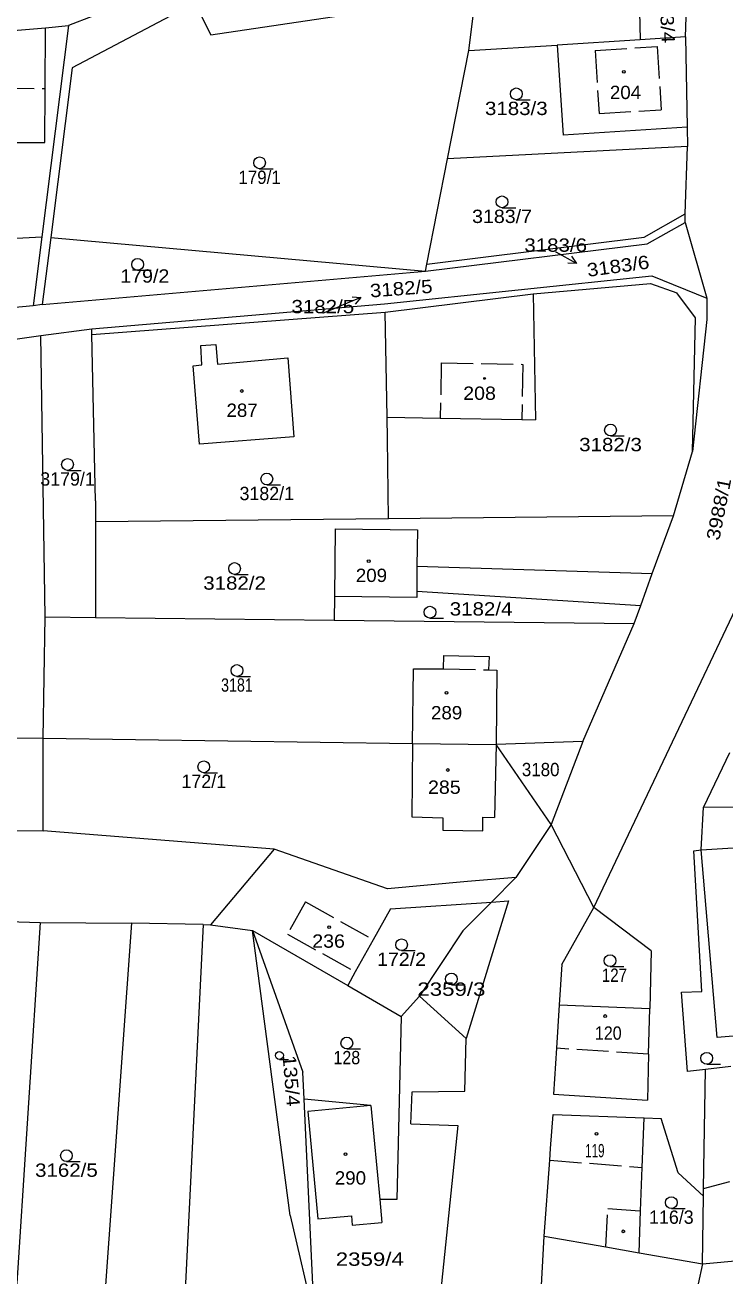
# Model space of a CAD drawing. Extents: x -590528 to -586543, y -1119609 to -1116685.
# Drawn here: x -588698 to -588608.7, y -1118281.3 to -1118121.8 of the extents above; entities that cross this region are included whole.
import ezdxf
from ezdxf.enums import TextEntityAlignment as Align

# ---------------------------------------------------------------- set-up
doc = ezdxf.new("R2010")
doc.units = 0
doc.header["$LTSCALE"] = 0.68
doc.linetypes.add('LONG_DASHED', pattern=[7.5, 6, -1.5])
for name, color, linetype, lineweight in [('1', 7, 'Continuous', 13), ('2', 7, 'LONG_DASHED', 13), ('3', 7, 'Continuous', 13), ('6', 7, 'Continuous', 13)]:
    doc.layers.add(name, color=color, linetype=linetype, lineweight=lineweight)

msp = doc.modelspace()

# ---------------------------------------------------------------- linework, layer by layer
at = {"layer": '1'}
for p, q in [((-588677.57, -1118116.13), (-588692.41, -1118121.83)), ((-588619.63, -1118115.95), (-588619.5, -1118123.67)), ((-588641.32, -1118125.05), (-588640.3, -1118116.83)), ((-588713.9, -1118123.63), (-588695.33, -1118122.16)), ((-588692.41, -1118121.83), (-588695.82, -1118148.8)), ((-588695.33, -1118122.16), (-588692.41, -1118121.83)), ((-588641.32, -1118125.05), (-588630.05, -1118124.34)), ((-588630.05, -1118124.34), (-588629.3, -1118135.83)), ((-588691.92, -1118127.24), (-588694.67, -1118148.9)), ((-588613.48, -1118134.81), (-588629.3, -1118135.83)), ((-588711.12, -1118136.71), (-588695.41, -1118136.78)), ((-588613.44, -1118137.3), (-588644.04, -1118138.87)), ((-588613.76, -1118146.98), (-588610.98, -1118156.63)), ((-588714.7, -1118149.82), (-588695.82, -1118148.8)), ((-588695.82, -1118148.8), (-588696.93, -1118157.62)), ((-588694.67, -1118148.9), (-588695.75, -1118157.42)), ((-588694.67, -1118148.9), (-588646.86, -1118153.18)), ((-588652.03, -1118158.43), (-588633.12, -1118156.09)), ((-588633.12, -1118156.09), (-588632.85, -1118172.15)), ((-588612.41, -1118159.15), (-588614.81, -1118155.95)), ((-588696.93, -1118157.62), (-588714.99, -1118159.28)), ((-588695.75, -1118157.42), (-588696.93, -1118157.62)), ((-588689.45, -1118160.52), (-588652.08, -1118157.36)), ((-588689.43, -1118161.26), (-588652.03, -1118158.43)), ((-588695.4, -1118197.29), (-588695.94, -1118161.41)), ((-588651.76, -1118171.81), (-588644.98, -1118171.93)), ((-588651.6, -1118184.77), (-588651.7, -1118174.57)), ((-588688.98, -1118182.48), (-588688.98, -1118185.17)), ((-588651.6, -1118184.77), (-588688.98, -1118185.17)), ((-588688.98, -1118185.17), (-588688.98, -1118197.36)), ((-588615.21, -1118184.38), (-588651.6, -1118184.77)), ((-588617.93, -1118191.74), (-588615.21, -1118184.38)), ((-588658.39, -1118186.06), (-588658.48, -1118194.7)), ((-588647.95, -1118190.83), (-588617.93, -1118191.74)), ((-588658.48, -1118194.7), (-588658.51, -1118197.7)), ((-588647.99, -1118194.02), (-588619.41, -1118195.81)), ((-588625.37, -1118234.33), (-588606.07, -1118193.71)), ((-588688.98, -1118197.36), (-588658.51, -1118197.7)), ((-588658.51, -1118197.7), (-588620.26, -1118198.13)), ((-588626.81, -1118213.18), (-588620.26, -1118198.13)), ((-588695.65, -1118212.77), (-588648.51, -1118213.43)), ((-588695.62, -1118224.58), (-588695.65, -1118212.77)), ((-588648.51, -1118213.43), (-588637.87, -1118213.55)), ((-588637.87, -1118213.55), (-588638.07, -1118222.85)), ((-588626.81, -1118213.18), (-588637.87, -1118213.55)), ((-588630.84, -1118223.78), (-588637.87, -1118213.55)), ((-588608.08, -1118214.62), (-588611.39, -1118221.57)), ((-588611.7, -1118227.01), (-588611.39, -1118221.57)), ((-588592.82, -1118221.58), (-588611.39, -1118221.57)), ((-588639.53, -1118224.55), (-588639.53, -1118222.84)), ((-588639.53, -1118222.84), (-588638.07, -1118222.85)), ((-588753.83, -1118223.97), (-588695.62, -1118224.58)), ((-588625.37, -1118234.33), (-588630.84, -1118223.78)), ((-588612.65, -1118227.1), (-588611.7, -1118227.01)), ((-588611.63, -1118245.06), (-588612.65, -1118227.1)), ((-588609.65, -1118250.91), (-588611.7, -1118227.01)), ((-588635.35, -1118230.51), (-588641.52, -1118231.05)), ((-588651.34, -1118234.53), (-588653.53, -1118238.46)), ((-588651.34, -1118234.53), (-588638.46, -1118233.65)), ((-588636.27, -1118233.5), (-588641.69, -1118251.06)), ((-588638.46, -1118233.65), (-588636.27, -1118233.5)), ((-588629.49, -1118241.6), (-588625.37, -1118234.33)), ((-588618.07, -1118239.88), (-588625.37, -1118234.33)), ((-588705.15, -1118235.97), (-588696.04, -1118236.25)), ((-588696.04, -1118236.25), (-588704.69, -1118371.28)), ((-588696.04, -1118236.25), (-588684.37, -1118236.36)), ((-588684.37, -1118236.36), (-588690.78, -1118326.07)), ((-588675.24, -1118236.53), (-588684.37, -1118236.36)), ((-588675.24, -1118236.53), (-588679.96, -1118332.69)), ((-588675.24, -1118236.53), (-588674.3, -1118236.55)), ((-588668.95, -1118237.26), (-588662.51, -1118255.33)), ((-588664.12, -1118273.62), (-588668.95, -1118237.26)), ((-588642.09, -1118237.31), (-588647.65, -1118245.64)), ((-588653.53, -1118238.46), (-588655.82, -1118242.57)), ((-588618.07, -1118239.88), (-588618.26, -1118247.21)), ((-588655.82, -1118242.57), (-588656.79, -1118244.3)), ((-588629.49, -1118241.6), (-588629.82, -1118246.78)), ((-588614.21, -1118245.16), (-588611.63, -1118245.06)), ((-588613.43, -1118255.27), (-588614.21, -1118245.16)), ((-588629.82, -1118246.78), (-588630.17, -1118252.31)), ((-588629.82, -1118246.78), (-588618.26, -1118247.21)), ((-588618.41, -1118253.05), (-588618.26, -1118247.21)), ((-588649.96, -1118248.26), (-588650.54, -1118271.58)), ((-588630.17, -1118252.31), (-588630.54, -1118258.15)), ((-588618.41, -1118253.05), (-588618.56, -1118258.91)), ((-588662.35, -1118258.78), (-588662.51, -1118255.33)), ((-588611.39, -1118270.2), (-588611.15, -1118255)), ((-588630.54, -1118258.15), (-588618.56, -1118258.91)), ((-588653.83, -1118259.6), (-588662.35, -1118258.78)), ((-588630.9, -1118265.08), (-588630.59, -1118260.75)), ((-588614.65, -1118268.2), (-588616.79, -1118261.25)), ((-588611.4, -1118271.16), (-588614.65, -1118268.2)), ((-588611.39, -1118270.2), (-588608.03, -1118269.31)), ((-588650.54, -1118271.58), (-588652.71, -1118271.58)), ((-588656.21, -1118274.87), (-588652.43, -1118274.53)), ((-588632.53, -1118291.22), (-588631.71, -1118276.27)), ((-588619.62, -1118278.38), (-588611.53, -1118279.79)), ((-588611.53, -1118279.79), (-588612.95, -1118286.29))]:
    msp.add_line(p, q, dxfattribs=at)
for points in [[(-588613.68, -1118123.3), (-588613.44, -1118115.68), (-588612.82, -1118096.34)], [(-588677.57, -1118116.13), (-588676.29, -1118118.98), (-588691.92, -1118127.24)], [(-588676.29, -1118118.98), (-588674.26, -1118123.02), (-588656.48, -1118120.41)], [(-588695.41, -1118136.78), (-588695.37, -1118129.88), (-588695.33, -1118122.16)], [(-588613.68, -1118123.3), (-588619.5, -1118123.67), (-588630.05, -1118124.34)], [(-588613.68, -1118123.3), (-588613.48, -1118134.81), (-588613.44, -1118137.3)], [(-588646.71, -1118152.3), (-588644.04, -1118138.87), (-588641.32, -1118125.05)], [(-588613.76, -1118146.98), (-588613.73, -1118145.86), (-588613.44, -1118137.3)], [(-588646.86, -1118153.18), (-588618.59, -1118149.71), (-588613.76, -1118146.98)], [(-588646.71, -1118152.3), (-588618.95, -1118148.86), (-588613.73, -1118145.86)], [(-588695.75, -1118157.42), (-588646.86, -1118153.18), (-588646.71, -1118152.3)], [(-588652.08, -1118157.36), (-588617.99, -1118153.76), (-588610.98, -1118156.63), (-588610.98, -1118159.33), (-588612.79, -1118176.18)], [(-588633.12, -1118156.09), (-588618.18, -1118154.74), (-588614.81, -1118155.95)], [(-588651.7, -1118174.57), (-588651.76, -1118171.81), (-588652.03, -1118158.43)], [(-588615.21, -1118184.38), (-588612.79, -1118176.18), (-588612.41, -1118159.15)], [(-588701.64, -1118162.19), (-588695.94, -1118161.41), (-588689.45, -1118160.52)], [(-588688.98, -1118182.48), (-588689.43, -1118161.26), (-588689.45, -1118160.52)], [(-588644.98, -1118171.93), (-588634.58, -1118172.12), (-588632.85, -1118172.15)], [(-588658.39, -1118186.06), (-588647.9, -1118186.18), (-588647.95, -1118190.83)], [(-588620.26, -1118198.13), (-588619.41, -1118195.81), (-588617.93, -1118191.74)], [(-588647.99, -1118194.02), (-588647.99, -1118194.82), (-588658.48, -1118194.7)], [(-588695.65, -1118212.77), (-588695.4, -1118197.29), (-588688.98, -1118197.36)], [(-588648.51, -1118213.43), (-588648.39, -1118203.92), (-588644.56, -1118203.89), (-588644.52, -1118202.19)], [(-588644.52, -1118202.19), (-588638.76, -1118202.35), (-588638.81, -1118204.05)], [(-588638.81, -1118204.05), (-588637.78, -1118204.06), (-588637.87, -1118213.55)], [(-588695.65, -1118212.77), (-588722.23, -1118212.91), (-588733.76, -1118212.97), (-588753.56, -1118213.07)], [(-588648.51, -1118213.43), (-588648.59, -1118222.77), (-588644.65, -1118222.93), (-588644.66, -1118224.47), (-588639.53, -1118224.55)], [(-588626.81, -1118213.18), (-588630.84, -1118223.78), (-588635.35, -1118230.51)], [(-588641.52, -1118231.05), (-588651.73, -1118231.95), (-588666.17, -1118226.91), (-588695.62, -1118224.58)], [(-588666.17, -1118226.91), (-588674.3, -1118236.55), (-588668.95, -1118237.26)], [(-588635.35, -1118230.51), (-588638.46, -1118233.65), (-588642.09, -1118237.31)], [(-588668.95, -1118237.26), (-588656.79, -1118244.3), (-588649.96, -1118248.26)], [(-588649.96, -1118248.26), (-588647.65, -1118245.64), (-588641.69, -1118251.06)], [(-588590.42, -1118249.31), (-588590.93, -1118249.35), (-588609.65, -1118250.91)], [(-588648.73, -1118261.95), (-588648.55, -1118257.85), (-588641.85, -1118257.76), (-588641.69, -1118251.06)], [(-588607.9, -1118254.61), (-588611.15, -1118255), (-588613.43, -1118255.27)], [(-588664.12, -1118273.62), (-588661.02, -1118287), (-588662.35, -1118258.78)], [(-588653.83, -1118259.6), (-588661.89, -1118260.36), (-588660.59, -1118274.06)], [(-588653.83, -1118259.6), (-588652.71, -1118271.58), (-588652.43, -1118274.53)], [(-588630.59, -1118260.75), (-588618.99, -1118261.17), (-588616.79, -1118261.25)], [(-588619.62, -1118278.38), (-588619.42, -1118273.04), (-588619.22, -1118267.53), (-588618.99, -1118261.17)], [(-588648.73, -1118261.95), (-588642.73, -1118262.17), (-588644.97, -1118283.56)], [(-588631.71, -1118276.27), (-588631.01, -1118266.56), (-588630.9, -1118265.08)], [(-588611.53, -1118279.79), (-588611.4, -1118271.16), (-588611.39, -1118270.2)], [(-588660.59, -1118274.06), (-588656.32, -1118273.68), (-588656.21, -1118274.87)], [(-588631.71, -1118276.27), (-588623.87, -1118277.64), (-588619.62, -1118278.38)], [(-588611.53, -1118279.79), (-588606.41, -1118279.31), (-588589.88, -1118277.78), (-588580.97, -1118277.25)]]:
    msp.add_lwpolyline(points, dxfattribs=at)
msp.add_lwpolyline([(-588663.64, -1118174.32), (-588675.68, -1118175.27), (-588676.51, -1118165.26), (-588675.38, -1118165.15), (-588675.52, -1118162.65), (-588673.6, -1118162.54), (-588673.39, -1118165.03), (-588664.44, -1118164.25)], close=True, dxfattribs=at)
at = {"layer": '2'}
for p, q in [((-588625.24, -1118125.03), (-588617.31, -1118124.53)), ((-588617.31, -1118124.53), (-588616.8, -1118132.59)), ((-588625.24, -1118125.03), (-588624.73, -1118133.09)), ((-588711.08, -1118129.79), (-588695.37, -1118129.88)), ((-588624.73, -1118133.09), (-588616.8, -1118132.59)), ((-588644.85, -1118164.88), (-588644.98, -1118171.93)), ((-588644.85, -1118164.88), (-588634.45, -1118165.07)), ((-588634.45, -1118165.07), (-588634.58, -1118172.12)), ((-588647.95, -1118190.83), (-588647.99, -1118194.02)), ((-588644.56, -1118203.89), (-588638.81, -1118204.05)), ((-588611.7, -1118227.01), (-588592.18, -1118225.62)), ((-588662.18, -1118233.64), (-588653.53, -1118238.46)), ((-588618.41, -1118253.05), (-588630.17, -1118252.31)), ((-588631.01, -1118266.56), (-588619.22, -1118267.53))]:
    msp.add_line(p, q, dxfattribs=at)
for points in [[(-588662.18, -1118233.64), (-588664.47, -1118237.75), (-588655.82, -1118242.57)], [(-588623.87, -1118277.64), (-588623.59, -1118272.75), (-588619.42, -1118273.04)]]:
    msp.add_lwpolyline(points, dxfattribs=at)
at = {"layer": '3'}
for p, q in [((-588630.26, -1118150.71), (-588630.21, -1118150.74)), ((-588627.589, -1118152.2), (-588630.21, -1118150.74)), ((-588655.123, -1118156.531), (-588657.89, -1118157.69)), ((-588659.96, -1118158.55), (-588657.89, -1118157.69))]:
    msp.add_line(p, q, dxfattribs=at)
for points in [[(-588628.22, -1118151.278), (-588627.589, -1118152.2), (-588628.707, -1118152.151)], [(-588656.238, -1118156.457), (-588655.123, -1118156.531), (-588655.852, -1118157.38)]]:
    msp.add_lwpolyline(points, dxfattribs=at)
at = {"layer": '6'}
for p, q in [((-588635.28, -1118131.32), (-588633.53, -1118131.32)), ((-588668.03, -1118140.11), (-588666.28, -1118140.11)), ((-588637.1, -1118145.09), (-588635.35, -1118145.09)), ((-588683.59, -1118153.07), (-588681.84, -1118153.07)), ((-588623.26, -1118174.2), (-588621.51, -1118174.2)), ((-588692.53, -1118178.59), (-588690.78, -1118178.59)), ((-588667.11, -1118180.44), (-588665.36, -1118180.44)), ((-588671.22, -1118191.86), (-588669.47, -1118191.86)), ((-588646.3, -1118197.43), (-588644.55, -1118197.43)), ((-588670.92, -1118204.87), (-588669.17, -1118204.87)), ((-588675.15, -1118217.15), (-588673.4, -1118217.15)), ((-588649.92, -1118239.85), (-588648.17, -1118239.85)), ((-588623.32, -1118241.88), (-588621.57, -1118241.88)), ((-588643.56, -1118244.22), (-588641.81, -1118244.22)), ((-588665.5, -1118253.722), (-588664.328, -1118253.722)), ((-588656.9, -1118252.39), (-588655.15, -1118252.39)), ((-588610.99, -1118254.33), (-588609.24, -1118254.33)), ((-588692.67, -1118266.75), (-588690.92, -1118266.75)), ((-588615.5, -1118272.74), (-588613.75, -1118272.74))]:
    msp.add_line(p, q, dxfattribs=at)
for centre, radius in [((-588621.5602, -1118127.7704), 0.175), ((-588635.28, -1118130.57), 0.75), ((-588668.03, -1118139.36), 0.75), ((-588637.1, -1118144.34), 0.75), ((-588683.59, -1118152.32), 0.75), ((-588639.3201, -1118166.8602), 0.1172), ((-588670.3102, -1118168.4704), 0.175), ((-588623.26, -1118173.45), 0.75), ((-588692.53, -1118177.84), 0.75), ((-588667.11, -1118179.69), 0.75), ((-588654.1102, -1118190.1604), 0.175), ((-588671.22, -1118191.11), 0.75), ((-588646.3, -1118196.68), 0.75), ((-588670.92, -1118204.12), 0.75), ((-588644.1702, -1118206.9504), 0.175), ((-588675.15, -1118216.4), 0.75), ((-588644.0202, -1118216.8104), 0.175), ((-588659.1502, -1118236.8404), 0.175), ((-588649.92, -1118239.1), 0.75), ((-588623.32, -1118241.13), 0.75), ((-588643.56, -1118243.47), 0.75), ((-588623.9402, -1118248.1904), 0.175), ((-588656.9, -1118251.64), 0.75), ((-588665.5, -1118253.22), 0.5025), ((-588610.99, -1118253.58), 0.75), ((-588625.0502, -1118263.2004), 0.175), ((-588692.67, -1118266), 0.75), ((-588657.0702, -1118265.8104), 0.175), ((-588615.5, -1118271.99), 0.75), ((-588621.6302, -1118275.6504), 0.175)]:
    msp.add_circle(centre, radius, dxfattribs=at)

# ---------------------------------------------------------------- texts
at = {"layer": '3', "width": 1.15}
for s, rotation, p in [('3183/4', 272.671, (-588616.9179, -1118120.1294)), ('3988/1', 78.839, (-588608.6178, -1118183.686)), ('135/4', 274.733, (-588664.8246, -1118256.5299))]:
    msp.add_text(s, height=1.7, rotation=rotation, dxfattribs=at).set_placement(p, align=Align.CENTER)
at = {"layer": '3'}
for s, width, p in [('204', 1.05, (-588621.3505, -1118131.23)), ('3183/3', 1.15, (-588635.28, -1118133.27)), ('179/1', 0.95, (-588668.0305, -1118142.06)), ('3183/7', 1.1, (-588637.1, -1118147.04)), ('3183/6', 1.15, (-588630.26, -1118150.71)), ('179/2', 1.1, (-588682.6705, -1118154.65)), ('3182/5', 1.15, (-588659.9595, -1118158.55)), ('208', 1.1, (-588639.9705, -1118169.6)), ('287', 1.05, (-588670.26, -1118171.77)), ('3182/3', 1.15, (-588623.2605, -1118176.15)), ('209', 1.05, (-588653.7605, -1118192.83)), ('3182/2', 1.15, (-588671.221, -1118193.81)), ('3182/4', 1.15, (-588639.7705, -1118197.11)), ('3181', 0.8, (-588670.92, -1118206.82)), ('289', 1.05, (-588644.1705, -1118210.35)), ('3180', 0.95, (-588632.1705, -1118217.6)), ('285', 1.1, (-588644.46, -1118219.85)), ('236', 1.1, (-588659.2305, -1118239.48)), ('172/2', 1.1, (-588649.92, -1118241.8)), ('2359/3', 1.25, (-588643.56, -1118245.61)), ('128', 0.9, (-588656.9, -1118254.34)), ('119', 0.65, (-588625.26, -1118266.21)), ('3162/5', 1.15, (-588692.6705, -1118268.7)), ('290', 1.05, (-588656.4405, -1118269.69)), ('2359/4', 1.25, (-588653.9705, -1118280.05))]:
    msp.add_text(s, height=1.7, dxfattribs=dict(at, width=width)).set_placement(p, align=Align.CENTER)
at = {"layer": '3', "width": 1.15}
for s, rotation, p in [('3183/6', 7.792, (-588626.144, -1118153.912)), ('3182/5', 4.354, (-588653.883, -1118156.542))]:
    msp.add_text(s, height=1.7, rotation=rotation, dxfattribs=at).set_placement(p)
at = {"layer": '3'}
for s, p in [('3179/1', (-588692.53, -1118180.54)), ('3182/1', (-588667.1105, -1118182.39)), ('172/1', (-588675.1505, -1118219.1)), ('116/3', (-588615.5, -1118274.69))]:
    msp.add_text(s, height=1.7, dxfattribs=at).set_placement(p, align=Align.CENTER)
for s, width, p in [('127', 0.85, (-588624.377, -1118243.83)), ('120', 0.9, (-588625.257, -1118251.21))]:
    msp.add_text(s, height=1.7, dxfattribs=dict(at, width=width)).set_placement(p)

doc.saveas('drawing.dxf')
